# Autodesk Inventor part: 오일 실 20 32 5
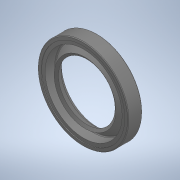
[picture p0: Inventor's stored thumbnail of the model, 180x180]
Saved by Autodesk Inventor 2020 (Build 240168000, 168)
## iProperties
Created: 2024-04
Part Number: 오일 실 20 32 5
Material: 고무
Description: 오일 실 - 비스프링, 조립 GA
Document SubType Name: Modeling
Designer: oem
Density: 0.93 g/cm^3
Appearance: 기본값
Author: jhkim
Sending System: Autodesk Inventor 2025
Preprocessor: ST-DEVELOPER v20
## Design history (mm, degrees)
feature "Solid1"
node "솔리드1"
